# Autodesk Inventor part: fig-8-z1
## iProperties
Created: 2009-04
Part Number: fig-8-z1
Document SubType Name: Modeling
Designer: Sham
Density: 1 g/cm^3
Author: Sham
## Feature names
1. Extrusion2
2. Split8
